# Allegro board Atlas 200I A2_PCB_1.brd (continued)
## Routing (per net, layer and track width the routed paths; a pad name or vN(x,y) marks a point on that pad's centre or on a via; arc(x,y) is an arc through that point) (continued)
PHY0_MDI2_P: length 29.3
  TOP w0.508: T19.20 v1(10,29.37)
  ART04 w0.356: v1(10,29.37) 9.88,29.24 9.88,28.59 10.78,27.68 10.78,27.01 11.14,26.65 11.52,26.65 11.88,26.3 11.88,25.59 11.52,25.23 11.14,25.23 10.78,24.88 10.78,21.94 11.14,21.58 11.58,21.58 11.93,21.23 11.93,20.51 11.58,20.16 11.14,20.16 9.61,18.63 9.61,16.84 11,15.45 11.49,15.45 11.85,15.81 11.85,15.86 12.21,16.22 12.92,16.22 13.27,15.86 13.27,15.81 13.63,15.45 16.92,15.45 18.69,13.69 J17.4
PHY0_MDI3_N: length 40.1
  TOP w0.508: T19.22 v1(12,29.37)
  ART03 w0.356: J17.8 23.77,14.03 22.36,15.43 10.55,15.43 9.56,16.42 9.56,18.76 10.83,20.04 10.83,24.93 12.17,26.26 13.94,26.26 15.7,28.02 15.7,30.31 14.9,31.11 13.06,31.11 12.15,30.2 12.15,29.51 v1(12,29.37)
PHY0_MDI3_P: length 40.1
  TOP w0.508: T19.23 v1(13,29.37)
  ART03 w0.356: v1(13,29.37) 12.91,29.46 12.91,29.88 13.38,30.35 14.58,30.35 14.94,29.99 14.94,28.34 13.62,27.03 11.85,27.03 10.07,25.24 10.07,20.35 8.79,19.07 8.79,16.11 10.23,14.67 11.11,14.67 11.37,14.4 12.64,14.4 12.91,14.67 22.05,14.67 22.5,14.22 J17.7
PHY1_MDI0_N: length 41.9
  TOP w0.508: T20.13 v1(18.93,29.37)
  ART03 w0.356: v1(18.93,29.37) 18.93,29.82 20.54,31.44 31.25,31.44 32.31,30.37 32.72,29.42 32.72,26.06 28.79,22.13 28.53,21.51 28.53,20.77 29.89,19.41 29.89,16.29 28.74,15.13 25.9,15.13 23.59,17.44 23.02,17.44 J17.10
PHY1_MDI0_P: length 41.8
  TOP w0.508: T20.14 v1(19.93,29.37)
  ART03 w0.356: v1(19.93,29.37) 19.93,29.74 20.86,30.67 30.93,30.67 31.67,29.94 31.96,29.27 31.96,28.91 31.6,28.55 31.54,28.55 31.18,28.19 31.18,27.48 31.54,27.13 31.6,27.13 31.96,26.77 31.96,26.38 30.46,24.88 29.96,24.88 29.41,25.44 28.9,25.44 28.4,24.93 28.4,24.43 28.95,23.88 28.96,23.37 28.15,22.56 27.77,21.66 27.77,20.46 29.13,19.1 29.13,16.6 28.42,15.9 26.21,15.9 25.58,16.52 25.58,17.03 25.82,17.27 25.82,17.77 25.32,18.27 24.82,18.27 24.58,18.03 24.07,18.03 23.77,18.34 J17.9
PHY1_MDI1_N: length 15.4
  TOP w0.508: T20.16 v1(21.93,29.37)
  ART04 w0.356: v1(21.93,29.37) 22.03,29.26 22.03,27.64 19.58,25.19 17.42,19.96 J17.14
PHY1_MDI1_P: length 15.4
  TOP w0.508: T20.17 v1(22.93,29.37)
  ART04 w0.356: v1(22.93,29.37) 22.8,29.23 22.8,27.32 22.36,26.89 22.36,26.39 22.76,25.99 22.76,25.49 22.26,24.98 21.76,24.98 21.36,25.38 20.85,25.38 20.23,24.76 19.2,22.29 19.2,21.6 19.61,20.63 20.78,19.46 J17.11
PHY1_MDI2_N: length 29.7
  TOP w0.508: T20.19 v1(24.93,29.37)
  ART04 w0.356: J17.13 19.17,19.46 21.21,17.42 21.21,16.04 21.86,15.38 28.24,15.38 29.26,16.4 29.26,19.04 27.81,20.49 27.81,25.52 25.04,28.29 25.04,29.26 v1(24.93,29.37)
PHY1_MDI2_P: length 29.8
  TOP w0.508: T20.20 v1(25.93,29.37)
  ART04 w0.356: J17.12 20.45,16.43 20.45,15.72 21.55,14.62 28.56,14.62 30.02,16.08 30.02,19.36 28.57,20.81 28.57,23.15 28.93,23.5 29.21,23.5 29.57,23.86 29.57,24.57 29.21,24.93 28.93,24.93 28.57,25.28 28.57,25.84 25.8,28.61 25.8,29.24 v1(25.93,29.37)
PHY1_MDI3_N: length 23.8
  TOP w0.508: T20.22 v1(27.93,29.37)
  ART03 w0.356: v1(27.93,29.37) 27.93,28.45 26.95,27.47 22.29,27.47 16.89,22.07 15.29,22.07 13.9,20.68 13.9,18.91 14.88,17.93 J17.16
PHY1_MDI3_P: length 23.8
  TOP w0.508: T20.23 v1(28.93,29.37)
  ART03 w0.356: J17.15 16.15,19.41 15.55,18.82 15.07,18.82 14.66,19.23 14.66,20.36 15.61,21.31 17.2,21.31 18.58,22.69 18.66,22.69 19.16,22.69 19.88,23.4 19.88,23.48 19.88,23.98 20.59,24.7 20.67,24.7 21.17,24.7 21.89,25.41 21.89,25.49 21.89,26 22.6,26.71 27.27,26.71 28.93,28.37 v1(28.93,29.37)
POWER_EN: length 17.6
  TOP w0.203: v1(103.58,53.19) 103,53.76 J16.301 ; R480.1 104.19,43.76 103.81,43.39 103.34,43.39 103.29,43.43 U16.1
  TOP w0.254: v1(103.48,43.89) 103.48,43.97 103.89,44.37 R480.1
  ART04 w0.203: v1(103.58,53.19) 102.54,52.15 102.54,49.28 104.1,47.71 104.1,44.52 v1(103.48,43.89)
PWM1: length 29.9
  TOP w0.203: J16.286 106.25,50.54 105.97,50.81 105.97,52.54 v1(107.64,54.2) ; R676.1 v1(120.11,68.23)
  ART03 w0.203: v1(107.64,54.2) 108.42,54.2 108.55,54.08 111.34,54.08 113.72,56.46 113.72,60.92 118.92,66.12 118.92,67.88 118.77,68.03 118.77,68.43 119.05,68.72 119.63,68.72 v1(120.11,68.23)
PWM1_R: length 40.7
  TOP w0.203: R443.1 122.94,101.6 v1(122.87,101.6) ; v1(119.08,78.96) 119.4,78.64 U21.12
  ART03 w0.203: v1(122.87,101.6) 122.87,101.23 121.34,99.69 121.34,90.9 120.46,90.02 114.86,90.02 111.48,86.63 111.48,79.19 112.21,78.46 118.58,78.46 v1(119.08,78.96)
RGMII0_MDCK: length 45.3
  TOP w0.203: R117.1 R118.2 25.45,69.52 25.93,70 R129.1 26.57,70.48 v1(26.57,70.49) ; v1(55.26,46.99) 55.25,47 J16.170
  ART04 w0.203: v1(26.57,70.49) 27.09,69.96 31.34,69.96 40.81,60.5 40.81,58.12 44.32,54.61 46.7,54.61 49.79,51.52 50.37,51.52 51.97,49.91 52.34,49.91 v1(55.26,46.99)
RGMII0_MDIO: length 47
  TOP w0.203: J16.172 54.75,47.51 v1(54.22,46.98) ; R128.1 R119.2 17.39,46.93 17.14,47.17 17.14,48.39 v1(17.02,48.51)
  ART04 w0.203: v1(17.02,48.51) 17.75,49.25 25.61,49.25 27.8,48.34 38.14,48.34 39.73,49.93 39.73,50.23 42.29,52.78 46.92,52.78 50.68,49.02 52.18,49.02 v1(54.22,46.98)
RGMII0_RST: length 38.8
  TOP w0.203: J16.174 54.25,50.49 54.08,50.66 54.08,52.58 v1(54.69,53.19) ; v1(72.06,71.01) R173.2 R568.2 R623.1
  ART03 w0.203: v1(72.06,71.01) 72.06,71.01 71.59,70.53 69.3,70.53 68.56,71.27 66.49,71.27 61.56,66.35 61.56,55.67 59.08,53.19 v1(54.69,53.19)
RGMII0_RST_R: length 86.1
  TOP w0.203: v1(24.43,72.77) R127.1 C264.1 R126.2 ; R615.2 v1(73.88,77.33) ; U1.13 15.28,51.39 v1(16.72,50.43)
  ART03 w0.203: v1(16.72,50.43) 16.72,50.76 16.38,51.1 16.38,56.21 16.48,56.31 16.48,56.72 16.38,56.82 16.38,59.82 16.72,60.15 16.72,60.18 17.3,60.76 17.3,64.49 23.83,71.02 24.71,71.02 25.07,71.38 25.07,72.14 v1(24.43,72.77)
  BOTTOM w0.203: v1(73.88,77.33) 71.85,79.36 53.9,79.36 50.52,75.97 28.22,75.97 25.02,72.77 v1(24.43,72.77)
RGMII0_RXCK: length 5.8
  TOP w0.203: J16.202 47.25,47.17 46.94,46.86 45.15,46.86 44.05,45.75 R111.2
RGMII0_RXD0: length 5
  TOP w0.203: R107.2 45.76,45.61 46.3,46.14 47.23,46.14 48.25,47.16 J16.198
RGMII0_RXD1: length 4.5
  TOP w0.203: J16.196 48.75,47.16 47.38,45.79 46.93,45.79 46.62,45.47 R108.2
RGMII0_RXD2: length 4.1
  TOP w0.203: R109.2 47.47,45.38 49.25,47.16 J16.194
RGMII0_RXD3: length 4
  TOP w0.203: J16.192 49.75,47.03 48.33,45.61 R110.2
RGMII0_RXDV: length 5.3
  TOP w0.203: J16.200 47.75,47.16 47.09,46.5 45.84,46.5 44.91,45.57 R112.2
RGMII0_TXCK: length 51.7
  TOP w0.203: C121.1 v1(49.43,45.97) 50.29,46.84 50.29,46.85 50.75,47.3 J16.188 ; U1.21 16.85,54.59 v1(19,56.74)
  ART03 w0.203: v1(49.43,45.97) 49.43,52.68 47.05,55.06 38.26,55.06 35.9,54.08 33.44,54.08 30.73,52.95 28.33,52.95 27.61,53.67 24.29,53.67 24.11,53.49 24.11,53.21 23.93,53.04 23.68,53.04 23.5,53.21 23.5,53.49 23.33,53.67 23.07,53.67 22.89,53.49 22.89,53.21 22.72,53.04 22.46,53.04 22.28,53.21 22.28,53.49 22.11,53.67 21.67,53.67 19,56.34 v1(19,56.74)
RGMII0_TXD0: length 52.2
  TOP w0.203: U1.19 17.78,53.79 v1(20.73,56.74) ; C128.1 v1(51.16,45.97) 51.75,46.57 J16.184
  ART03 w0.203: v1(51.16,45.97) 51.16,49.18 51.34,49.36 51.34,50.59 50.93,51 50.93,52.96 49.48,54.41 49.48,54.91 49.2,55.19 48.7,55.19 47.62,56.27 38.02,56.27 35.88,55.39 35.87,55.38 35.66,55.3 31.48,55.3 30.25,55.8 26.31,55.8 25.4,54.89 22.17,54.89 20.73,56.33 v1(20.73,56.74)
RGMII0_TXD1: length 53
  TOP w0.203: v1(21.59,56.74) 18.24,53.39 U1.18 ; C135.1 v1(52.02,45.97) 52.25,46.2 J16.182
  ART03 w0.203: v1(21.59,56.74) 21.59,56.34 22.43,55.5 25.15,55.5 26.06,56.41 30.37,56.41 31.6,55.91 35.53,55.91 37.89,56.88 47.87,56.88 48.95,55.8 49.45,55.8 50.09,55.16 50.09,54.83 51.54,53.39 51.54,51.59 52.02,51.11 v1(52.02,45.97)
RGMII0_TXD2: length 53.7
  TOP w0.203: v1(22.45,56.74) 18.7,52.99 U1.17 ; C150.1 v1(52.88,45.97) 52.75,46.11 J16.180
  ART03 w0.203: v1(22.45,56.74) 23.09,56.11 24.89,56.11 25.81,57.02 30.62,57.02 31.85,56.52 35.41,56.52 37.77,57.49 48.12,57.49 49.2,56.41 49.71,56.41 50.7,55.42 50.7,55.09 52.15,53.64 52.15,51.87 52.63,51.38 52.63,46.59 v1(52.88,45.97)
RGMII0_TXD3: length 55
  TOP w0.203: U1.16 19.17,52.59 23.32,56.74 v1(23.32,56.74) ; C151.1 v1(53.75,45.97) 53.25,46.47 J16.178
  ART03 w0.203: v1(53.75,45.97) 53.24,47.2 53.24,52 52.86,52.38 52.86,54.54 50.27,57.12 49.53,57.12 48.55,58.1 37.65,58.1 35.29,57.12 31.97,57.12 30.75,57.63 25.56,57.63 24.67,56.74 v1(23.32,56.74)
RGMII0_TXEN: length 51.4
  TOP w0.203: J16.186 51.25,46.77 50.45,45.97 v1(50.29,45.97) C122.1 ; v1(19.86,56.74) 17.31,54.19 U1.20
  ART03 w0.203: v1(50.29,45.97) 50.29,49.17 50.73,49.62 50.73,50.33 50.29,50.77 50.29,52.74 47.36,55.67 38.14,55.67 36,54.78 35.78,54.69 31.36,54.69 30.13,55.19 26.59,55.19 25.68,54.28 21.92,54.28 19.86,56.34 v1(19.86,56.74)
RGMII1_MDCK: length 22.5
  TOP w0.203: v1(66.5,35.89) 67.02,35.89 R176.1 67.25,35.66 R175.2 ; J16.134 64.25,49.74 64.45,49.95 64.74,49.95 65.02,49.66 v1(65.02,48.77)
  TOP w0.254: v1(66.5,35.89) R183.1
  BOTTOM w0.203: v1(65.02,48.77) 65.23,48.97 66.37,48.97 67.27,48.07 67.27,45.17 69.06,43.38 69.06,37.99 66.96,35.89 v1(66.5,35.89)
RGMII1_MDIO: length 19.2
  TOP w0.203: v1(65.02,47.88) 65.02,47.5 64.82,47.3 63.95,47.3 63.75,47.5 J16.136 ; v1(66.5,36.74) 66.56,36.68 R174.2
  TOP w0.254: v1(66.5,36.74) R182.1
  BOTTOM w0.203: v1(65.02,47.88) 65.51,48.36 66.11,48.36 66.66,47.82 66.66,44.92 68.05,43.53 68.05,37.83 66.96,36.74 v1(66.5,36.74)
RGMII1_RST: length 54.5
  TOP w0.203: R564.2 R622.1 R200.2 69.5,77.28 v1(69.49,77.29) ; v1(64.87,52.74) 64.87,52.28 63.25,50.66 J16.138
  ART03 w0.203: v1(53.31,68.11) v1(53.31,77)
  ART04 w0.203: v1(53.31,68.11) 54.75,68.11 64.54,58.32 64.54,56.91 64.87,56.58 v1(64.87,52.74)
  BOTTOM w0.203: v1(69.49,77.29) 68.03,78.75 55.07,78.75 v1(53.31,77)
RGMII1_RST_R: length 90
  TOP w0.203: v1(68.12,34.37) 67.94,34.19 66.93,34.19 66.65,33.91 66.65,32.84 66.45,32.64 65.05,32.64 ; 65.05,32.64 R195.1 C265.1 ; 65.05,32.64 R194.2 64.5,31.44 61.88,31.44 61.35,31.96 U2.13 ; R614.2 v1(73.88,78.44)
  ART03 w0.203: v1(51.18,78.61) 50.86,78.29 50.86,69.29 v1(52.04,68.11)
  ART04 w0.203: v1(68.12,34.37) 68.12,41.39 66.44,43.07 65.54,45.25 65.54,46.01 64.76,46.79 61.77,46.79 51.59,56.97 51.59,67.65 v1(52.04,68.11)
  BOTTOM w0.203: v1(51.18,78.61) 52.3,78.61 54.63,80.94 71.37,80.94 v1(73.88,78.44)
RGMII1_RXCK: length 12.8
  TOP w0.203: J16.166 56.25,47 v1(56.26,46.99)
  TOP w0.254: v1(61.89,42.58) R159.2
  BOTTOM w0.203: v1(56.26,46.99) 56.26,43.92 57.4,42.77 59.23,42.77 59.43,42.57 59.43,42.14 59.64,41.94 60.04,41.94 60.25,42.14 60.25,42.57 60.45,42.77 61.69,42.77 v1(61.89,42.58)
RGMII1_RXD0: length 13.4
  TOP w0.203: v1(57.28,45.97) 57.28,46.1 57.25,46.13 J16.162
  TOP w0.254: v1(64.97,43.21) R163.2
  BOTTOM w0.203: v1(57.28,45.97) 59.06,44.19 61.26,44.19 62.23,43.21 62.74,43.21 62.94,43.01 62.94,42.55 63.14,42.34 63.55,42.34 63.75,42.55 63.75,43.01 63.96,43.21 v1(64.97,43.21)
RGMII1_RXD1: length 9.9
  TOP w0.203: v1(57.78,46.99) 57.75,47.02 J16.160
  TOP w0.254: v1(64.97,45.75) R162.2
  BOTTOM w0.203: v1(57.78,46.99) 58.27,46.51 63.15,46.51 64.96,45.76 v1(64.97,45.75)
RGMII1_RXD2: length 12.5
  TOP w0.203: J16.158 58.25,47.41 58.29,47.36 v1(58.29,45.97)
  TOP w0.254: v1(65.61,42.58) R161.2
  BOTTOM w0.203: v1(65.61,42.58) 65.61,43.26 65.01,43.86 64.08,43.86 62.96,44.98 59.21,44.98 58.29,45.9 v1(58.29,45.97)
RGMII1_RXD3: length 17
  TOP w0.203: J16.156 58.75,47.04 v1(58.8,46.99)
  TOP w0.254: v1(66.5,39.41) R160.2
  BOTTOM w0.203: v1(66.5,39.41) 66.29,39.61 66.29,44.15 65.99,44.45 65.99,45.95 64.62,47.31 59.12,47.31 v1(58.8,46.99)
RGMII1_RXDV: length 15.9
  TOP w0.203: J16.164 56.75,46.75 56.39,46.39 54.69,46.39 54.39,46.09 54.39,45.52 54.59,45.31 54.99,45.31 55.19,45.52 55.19,45.77 55.4,45.98 55.8,45.98 56,45.77 56,45.52 56.21,45.31 58.53,45.31 58.73,45.11 58.73,44.69 58.56,44.51 58.47,44.51 58.29,44.33 58.29,44.08 58.47,43.9 58.56,43.9 58.73,43.73 58.73,43.32 59.29,42.77 59.54,42.77 59.72,42.95 59.72,43.38 59.94,43.6 60.22,43.6 60.4,43.43 60.4,42.89 R158.2
RGMII1_TXCK: length 20.3
  TOP w0.203: J16.152 59.75,46.21 v1(59.33,45.79) ; v1(63.37,35.46) 62.87,35.96 62.3,35.96 61.5,35.16 U2.21
  TOP w0.254: C154.1 59.39,45.21 59.39,45.73 v1(59.33,45.79)
  ART03 w0.203: v1(63.37,35.46) 62.89,34.98 62.05,34.98 60.09,36.94 60.09,39.22 59.81,39.49 59.81,43.91 59.33,44.39 v1(59.33,45.79)
RGMII1_TXD0: length 19.6
  TOP w0.203: v1(61.06,45.79) 60.75,46.09 J16.148 ; v1(63.37,34.37) 62.89,34.85 62.26,34.85 61.77,34.36 U2.19
  TOP w0.254: v1(61.06,45.79) C160.1
  ART03 w0.203: v1(63.37,34.37) 63.96,34.95 63.96,35.77 62.79,36.93 62.79,38.06 62.64,38.2 62.64,38.94 61.41,40.18 61.41,42.78 61.54,42.91 61.54,43.91 61.06,44.39 v1(61.06,45.79)
RGMII1_TXD1: length 20.4
  TOP w0.203: J16.146 61.25,46.46 v1(61.92,45.79) ; v1(62.56,34.37) 62.33,34.37 61.93,33.96 U2.18
  TOP w0.254: v1(61.92,45.79) C166.1
  ART03 w0.203: v1(61.92,45.79) 61.92,44.39 62.15,44.16 62.15,43 63.25,41.9 63.25,38.91 64.57,37.6 64.57,34.7 63.75,33.88 63.04,33.88 v1(62.56,34.37)
RGMII1_TXD2: length 21.4
  TOP w0.203: v1(62.78,45.79) 61.75,46.82 J16.144 ; U2.17 62.09,33.56 62.26,33.73 62.92,33.73 v1(63.37,33.27)
  TOP w0.254: v1(62.78,45.79) C174.1
  ART03 w0.203: v1(63.37,33.27) 64.01,33.27 65.18,34.44 65.18,37.85 63.86,39.16 63.86,43.31 62.78,44.39 v1(62.78,45.79)
RGMII1_TXD3: length 22.4
  TOP w0.203: J16.142 62.25,47.35 63.65,45.95 C178.1 ; U2.16 62.45,33.16 v1(62.56,33.27)
  TOP w0.254: v1(64.28,45.15) C178.1
  ART03 w0.203: v1(62.56,33.27) 63.17,32.66 64.26,32.66 65.79,34.19 65.79,38.1 64.49,39.4 64.49,43.87 64.77,44.14 64.77,44.67 v1(64.28,45.15)
RGMII1_TXEN: length 16.9
  TOP w0.203: v1(62.56,35.46) 62.31,35.46 61.61,34.76 U2.20 ; J16.150 60.25,45.84 v1(60.19,45.79)
  TOP w0.254: v1(60.19,45.79) C159.1
  ART03 w0.203: v1(62.56,35.46) 62.56,35.92 62.18,36.3 62.18,37.81 61.23,38.75 61.23,39.06 60.42,39.87 60.42,44.16 60.19,44.39 v1(60.19,45.79)
RGMII_CLK_PHY0: length 60.4
  TOP w0.203: R96.2 v1(42.88,41.2) R100.1 43.26,41.83 43.51,42.09 43.51,43.48 44.05,44.03 R111.1 ; C109.1 12.19,59.03 12.7,58.52 v1(12.7,58.17) 12.75,58.11 U1.28
  ART03 w0.203: v1(42.88,41.2) 42.65,41.43 41.96,41.43 41.43,40.89 40.92,40.89 40.77,41.05 40.77,41.43 40.56,41.63 39.91,41.63 39.7,41.43 39.7,41.07 39.5,40.87 39.09,40.87 38.89,41.07 38.89,41.43 38.69,41.63 38.28,41.63 38.08,41.43 38.08,41.07 37.87,40.87 37.47,40.87 37.26,41.07 37.26,41.43 37.06,41.63 36.66,41.63 36.45,41.43 36.45,41.07 36.25,40.87 35.84,40.87 35.64,41.07 35.64,41.43 35.44,41.63 35.11,41.63 35.08,41.66 34.9,41.66 34.7,41.86 34.7,42.14 34.16,42.67 31.24,42.67 30.44,43.21 27.9,43.21 27.7,43.41 27.7,43.87 27.5,44.07 27.09,44.07 26.89,43.87 26.89,43.41 26.68,43.21 26.28,43.21 26.07,43.41 26.07,43.87 25.87,44.07 25.46,44.07 25.26,43.87 25.26,43.41 25.06,43.21 24.65,43.21 24.45,43.41 24.45,43.87 24.25,44.07 23.84,44.07 23.64,43.87 23.64,43.41 23.43,43.21 23.03,43.21 22.82,43.41 22.82,43.87 22.62,44.07 22.21,44.07 22.01,43.87 22.01,43.41 21.81,43.21 19.77,43.21 17.2,44.27 16.1,45.36 16.1,46.15 15.13,47.12 14.12,47.12 12.3,48.94 12.3,55.1 12.7,55.5 v1(12.7,58.17)
RGMII_CLK_PHY1: length 9.1
  TOP w0.203: v1(59.12,38.07) 59.12,37.87 58.91,37.67 U2.28 ; v1(62.7,39.81) 63.34,40.45 R177.1 R152.2 R159.1
  TOP w0.254: v1(62.7,39.81) C44.1
  BOTTOM w0.203: v1(62.7,39.81) 62.19,39.81 60.45,38.07 v1(59.12,38.07)
RGMII_DV_PHY0: length 57.3
  TOP w0.203: v1(13.21,58.93) 13.31,58.83 13.31,57.96 13.15,57.81 U1.27 ; R92.2 44.15,41.19 v1(44.14,41.2) 44.15,41.21 R120.1 44.54,41.83 44.78,42.07 44.78,43.69 44.91,43.81 R112.1
  ART03 w0.203: v1(13.21,58.93) 13.03,59.11 11.79,59.11 11.28,58.6 9.83,55.1 9.83,50.54 10.74,48.34 11.3,47.78 11.3,46.6 11.51,46.39 11.51,46.37 12.13,45.75 12.15,45.75 13.36,44.54 20.2,41.71 30.49,41.71 32.2,40.56 32.48,40.56 33.04,40 33.3,39.83 35.63,39.37 40.06,39.37 43.89,40.95 v1(44.14,41.2)
RGMII_DV_PHY1: length 9.4
  TOP w0.203: U2.27 59.31,37.57 59.88,38.14 59.88,38.6 60.2,38.91 60.5,38.91 60.71,38.71 60.71,38.51 60.88,38.33 61.21,38.33 61.54,38.65 61.54,39.1 61.33,39.31 60.67,39.31 60.47,39.51 R181.1 R148.2 60.47,41.86 61.15,42.55 R158.1
RGMII_PHY0_D0: length 55.9
  TOP w0.203: U1.26 13.55,57.37 v1(13.72,57.53) ; R107.1 45.76,43.9 46.05,43.61 46.05,42.16 45.72,41.83 R141.1 45.43,41.81 45.43,41.22 v1(45.45,41.2) 45.43,41.18 45.43,40.58 R90.2
  ART03 w0.203: v1(45.45,41.2) 45.13,41.52 45.11,41.52 44.93,41.71 43.23,41.71 42.9,42.04 41.15,42.04 40.59,42.6 35.1,42.6 34.39,43.31 31.39,43.31 30.63,43.81 28.83,43.81 27.97,44.68 27.15,44.68 26.95,44.88 26.95,45.77 26.75,45.97 26.34,45.97 26.14,45.77 26.14,44.88 25.93,44.68 25.53,44.68 25.32,44.88 25.32,45.77 25.12,45.97 24.71,45.97 24.51,45.77 24.51,44.88 24.31,44.68 23.84,44.68 23.63,44.88 23.63,45.59 23.43,45.8 23.02,45.8 22.82,45.59 22.82,44.88 22.62,44.68 17.93,44.68 16.71,45.9 16.71,46.41 15.4,47.73 14.37,47.73 13.51,48.6 13.51,57.32 v1(13.72,57.53)
RGMII_PHY0_D1: length 63.3
  TOP w0.203: R108.1 46.62,44.06 47.32,43.36 47.32,42.06 47.09,41.83 R123.1 v1(46.69,41.2) R93.2 ; U1.25 13.95,57.01 14.22,57.28 v1(14.22,58.29)
  ART03 w0.203: v1(14.22,58.29) 14.22,58.77 13.28,59.72 11.53,59.72 10.76,58.95 9.22,55.22 9.22,50.29 9.98,48.47 9.98,47.86 10.56,46.46 11.83,45.19 11.85,45.19 13.16,43.88 20.05,41.03 30.41,41.03 32.02,39.95 32.23,39.95 32.51,39.67 32.51,39.62 33.05,39.26 35.57,38.76 40.42,38.76 45.02,40.67 45.69,40.67 46.48,40.99 v1(46.69,41.2)
RGMII_PHY0_D2: length 61.1
  TOP w0.203: R94.2 v1(47.96,41.2) R122.1 48.29,41.83 48.59,42.14 48.59,43.29 48.14,43.74 47.96,43.74 47.47,44.22 R109.1 ; v1(15.21,56.39) 15.08,56.26 15.08,56.01 14.87,55.79 U1.24
  ART03 w0.203: v1(47.96,41.2) 47.4,41.2 46.7,41.9 46.02,41.9 45.75,42.17 45.75,42.44 45.47,42.72 44.64,42.72 44.26,42.35 43.83,42.35 43.45,42.72 41.91,42.72 41.88,42.75 41.78,42.75 41.05,43.48 39.92,43.48 39.64,43.21 39.11,43.21 38.83,43.48 38.3,43.48 38.02,43.21 37.48,43.21 37.21,43.48 36.67,43.48 36.39,43.21 35.86,43.21 35.58,43.48 35.07,43.48 34.64,43.92 31.58,43.92 30.76,44.46 30.37,44.46 29.68,45.15 29.68,45.44 30.1,45.86 30.1,46.66 30.05,46.71 30.05,46.74 29.18,47.6 24.26,47.6 22.76,49.1 22.05,49.1 21.79,48.84 21.77,48.84 21.49,48.56 21.49,48.16 21.84,47.81 21.84,45.49 21.64,45.29 18.19,45.29 17.32,46.15 17.32,46.66 15.65,48.34 14.63,48.34 14.13,48.83 14.13,50.59 14.61,51.07 14.61,51.32 14.25,51.67 14.25,52.08 14.45,52.28 14.66,52.28 14.86,52.48 14.86,52.89 14.66,53.09 14.45,53.09 14.25,53.3 14.25,53.7 14.45,53.91 14.66,53.91 14.86,54.11 14.86,54.52 14.66,54.72 14.45,54.72 14.25,54.92 14.25,55.33 14.45,55.53 14.66,55.53 14.86,55.74 14.86,56.04 v1(15.21,56.39)
RGMII_PHY0_D3: length 65.1
  TOP w0.203: U1.23 15.48,55.39 v1(15.65,55.56) ; R95.2 49.38,40.72 v1(49.38,41.2) 49.83,41.66 R121.1 49.4,41.83 49.2,42.04 49.2,43.19 48.33,44.06 R110.1
  ART03 w0.203: v1(15.65,55.56) 15.65,49.22 15.71,49.17 15.71,49.14 18.12,46.73 18.19,46.73 18.47,46.44 18.47,46.38 18.95,45.9 20.6,45.9 21.01,46.3 21.01,47.78 20.88,47.91 20.88,48.81 21.52,49.45 21.54,49.45 21.79,49.71 24.26,49.71 24.57,49.39 24.57,49.11 24.36,48.9 24.36,48.61 24.74,48.23 25.18,48.23 25.39,48.44 25.39,48.74 25.59,48.95 26,48.95 26.2,48.74 26.2,48.44 26.4,48.23 26.81,48.23 27.01,48.44 27.01,48.74 27.22,48.95 27.62,48.95 27.83,48.74 27.83,48.44 28.03,48.23 29.44,48.23 30.9,46.77 30.9,45.3 31.11,45.09 31.78,45.09 32.13,44.73 33.16,44.73 33.36,44.93 33.36,45.64 33.57,45.85 33.97,45.85 34.18,45.64 34.18,44.93 34.38,44.73 34.69,44.73 35.33,44.09 35.74,44.09 35.95,44.3 35.95,44.81 36.15,45.01 36.56,45.01 36.76,44.81 36.76,44.3 36.96,44.09 37.37,44.09 37.57,44.3 37.57,44.81 37.78,45.01 38.18,45.01 38.39,44.81 38.39,44.3 38.59,44.09 39,44.09 39.2,44.3 39.2,44.81 39.4,45.01 39.81,45.01 40.01,44.81 40.01,44.3 40.21,44.09 41.33,44.09 41.71,44.48 42.14,44.48 42.52,44.09 42.95,44.09 43.33,44.48 43.76,44.48 44.14,44.09 44.58,44.09 44.96,44.48 45.39,44.48 45.77,44.09 46,44.09 46.2,43.89 46.2,43.08 46.77,42.51 46.95,42.51 47.52,41.94 48.64,41.94 v1(49.38,41.2)
RGMII_PHY1_D0: length 8.3
  TOP w0.203: R163.1 R147.2 R143.1 64.16,40.41 62.49,38.74 v1(62.16,38.74) 61.39,37.97 60.22,37.97 59.71,37.46 U2.26
RGMII_PHY1_D1: length 15.1
  TOP w0.203: R162.1 R180.1 66.53,44.3 R149.2 ; v1(60.73,37.44) 60.32,37.44 60.11,37.24 U2.25
  TOP w0.254: R149.2 v1(66.95,43.24)
  BOTTOM w0.203: v1(66.95,43.24) 66.98,43.21 66.98,38.3 66.7,38.02 62.13,38.02 v1(60.73,37.44)
RGMII_PHY1_D2: length 10.3
  TOP w0.203: R161.1 R150.2 R179.1 67.06,40.39 66.75,40.08 64.47,40.08 v1(61.41,37.03) 61.41,36.72 61.05,36.36 U2.24
RGMII_PHY1_D3: length 6.9
  TOP w0.203: R160.1 R178.1 R151.2 64.69,37.6 64.39,37.9 63.8,37.9 62.82,37.49 61.29,35.96 U2.23
SD_CLK: length 5.9
  TOP w0.381: J3.5 17.57,97.51 v1(17.88,97.82) 17.88,98.53 18.6,99.25 U3.4 19.73,100.11 19.91,100.29 R171.2
SD_CMD: length 11.2
  TOP w0.203: R226.2 v1(21.82,101.6)
  TOP w0.381: U3.6 19.73,97.11 v1(19.1,96.48) 17.93,95.31 J3.3
  ART03 w0.203: v1(19.1,96.48) 20.07,97.44 20.07,100.46 20.65,101.04 21.26,101.04 v1(21.82,101.6)
SD_DATA0: length 10.2
  TOP w0.203: U4.1 19.5,104.84 19.15,105.18 R227.2
  TOP w0.381: J3.7 17.64,99.71 v1(18,100.07) 19.91,101.98 20.19,101.98 20.95,102.74 20.95,104.45 20.57,104.84 U4.1
SD_DATA1: length 6.7
  TOP w0.381: R228.2 17.68,103.45 18.2,102.94 U4.3 v1(17.96,101.16) 17.6,100.81 J3.8
SD_DATA2: length 9.6
  TOP w0.381: R224.2 24.09,97.35 U3.1 21.87,97.35 21.49,96.97 21.49,96.16 v1(18.78,93.46) 18.43,93.11 J3.1
SD_DATA3: length 10.5
  TOP w0.381: R225.2 24.09,99.25 U3.3 21.59,99.25 20.7,98.36 20.7,96.49 v1(19.9,95.7) 18.42,94.21 J3.2
SDIO_CLK: length 81.8
  TOP w0.203: R309.1 R308.2 23.44,102.08 21.28,102.08 20.73,101.53 R171.1 ; J16.169 v1(55.5,58.83)
  TOP w0.381: R171.1 20.73,100.56 v1(20.95,100.33)
  ART03 w0.203: v1(55.5,58.83) 55.5,58.86 54.88,59.49 54.85,59.49 53.98,60.36 53.98,80.02 48.3,85.7 47.13,85.7 v1(45.42,87.41)
  ART04 w0.203: v1(45.42,87.41) 44.71,88.11 43.89,88.11 41.71,90.3 41.71,91.34 41.22,91.83 41.22,92.12 41.5,92.4 41.5,92.69 41.22,92.97 40.93,92.97 40.65,92.69 40.36,92.69 40.07,92.98 40.07,93.27 40.35,93.55 40.35,93.84 40.07,94.12 39.78,94.12 39.5,93.84 39.21,93.84 38.92,94.13 38.92,94.42 39.2,94.7 39.2,94.98 38.92,95.27 38.63,95.27 38.35,94.99 38.06,94.99 37.77,95.28 37.77,95.57 38.05,95.85 38.05,96.13 37.77,96.42 37.48,96.42 37.2,96.14 36.91,96.14 36.62,96.43 36.62,96.72 36.9,97 36.9,97.28 36.7,97.49 36.41,97.49 35.79,96.86 35.14,96.86 34.94,97.07 34.94,97.56 34.73,97.76 34.33,97.76 34.12,97.56 34.12,97.07 33.92,96.86 33.52,96.86 33.31,97.07 33.31,97.56 33.11,97.76 32.7,97.76 32.5,97.56 32.5,97.07 32.3,96.86 31.89,96.86 31.69,97.07 31.69,97.56 31.48,97.76 31.08,97.76 30.87,97.56 30.87,97.07 30.67,96.86 29.81,96.86 28.06,98.62 24.5,98.62 22.79,100.33 v1(20.95,100.33)
SDIO_CLK_R: length 13.7
  TOP w0.203: R86.2 v1(26.04,86.36) ; J2.9 20.17,79.64 v1(20.4,79.86)
  ART03 w0.203: v1(26.04,86.36) 26.77,85.62 26.77,83.26 23.55,80.04 20.57,80.04 v1(20.4,79.86)
SDIO_CMD: length 68
  TOP w0.203: v1(23.5,100.33) 23.5,100.71 R233.2 R226.1 ; v1(56,59.71) J16.167
  ART03 w0.203: v1(56,59.71) 55.12,60.59 55.12,79.74 48.55,86.31 47.42,86.31 46.81,86.92 v1(46.81,87.41)
  ART04 w0.203: v1(46.81,87.41) 46.81,88.27 45.12,89.97 43.97,89.97 43.15,90.78 43.15,92.86 35.97,100.05 26.59,100.05 26.24,99.69 24.79,99.69 24.16,100.33 v1(23.5,100.33)
SDIO_CMD_R: length 19.6
  TOP w0.203: J2.11 19.68,79.95 19.76,80.04 v1(19.76,81.13) ; R85.2 v1(25.97,92.08)
  ART03 w0.203: v1(25.97,92.08) 25.37,91.48 25.37,83.72 23.65,81.99 23.65,81.56 22.73,80.64 20.24,80.64 v1(19.76,81.13)
SDIO_DATA0: length 74.9
  TOP w0.203: J16.165 v1(56.5,58.83) ; v1(20.95,106.43) 20.95,106.38 20.75,106.17 R227.1 R232.2
  ART03 w0.203: v1(45.54,91.73) 45.42,91.73 44.75,91.07 44.75,88.78 45.52,88.02 45.67,88.02 47.06,88.02 47.52,87.56 47.52,87.21 47.81,86.92 48.8,86.92 55.73,79.99 55.73,60.83 56.5,60.06 v1(56.5,58.83)
  ART04 w0.203: v1(20.95,106.43) 30.28,102.57 36.3,102.57 45.54,93.32 v1(45.54,91.73)
SDIO_DATA0_R: length 13.5
  TOP w0.203: J2.13 19.17,80.44 v1(18.49,81.13) ; R84.2 v1(24.77,86.36)
  ART03 w0.203: v1(24.77,86.36) 24.77,84.41 24.28,83.92 22.28,83.92 20.09,81.74 19.51,81.74 18.9,81.13 v1(18.49,81.13)
SDIO_DATA1: length 76.7
  TOP w0.203: R228.1 R231.2 16.51,104.9 16.12,104.51 v1(16.12,104.15) ; J16.163 v1(57,59.71)
  ART03 w0.203: v1(46.81,89.19) 47.99,88.01 48.57,88.01 56.34,80.25 56.34,61.47 57,60.81 v1(57,59.71)
  ART04 w0.203: v1(16.12,104.15) 20.87,102.18 21.82,102.18 24.95,100.89 36.07,100.89 43.79,93.17 43.79,91.52 44.67,90.64 45.36,90.64 v1(46.81,89.19)
SDIO_DATA1_R: length 18.9
  TOP w0.203: v1(18.49,79.86) 18.68,79.67 J2.15 ; R83.2 v1(24.7,92.08)
  ART03 w0.203: v1(24.7,92.08) 24.16,91.53 24.16,85.7 22.98,84.53 22.02,84.53 19.84,82.35 19.26,82.35 18.65,81.74 18.24,81.74 17.88,81.38 17.88,80.47 v1(18.49,79.86)
SDIO_DATA2: length 71.3
  TOP w0.203: J16.161 v1(57.5,58.84) ; v1(26.87,99.39) 25.68,98.2 R230.2 R224.1
  ART03 w0.203: v1(57.5,58.84) 57.5,62.27 56.95,62.82 56.95,80.5 48.82,88.62 48.24,88.62 47.06,89.8 46.41,89.8 v1(45.42,88.81)
  ART04 w0.203: v1(45.42,88.81) 44.93,89.29 43.78,89.29 42.39,90.68 42.39,92.66 35.66,99.39 34.33,99.39 34.13,99.19 34.13,98.73 33.93,98.53 33.52,98.53 33.32,98.73 33.32,99.19 33.11,99.39 32.71,99.39 32.5,99.19 32.5,98.73 32.3,98.53 31.89,98.53 31.69,98.73 31.69,99.19 31.49,99.39 31.08,99.39 30.88,99.19 30.88,98.73 30.67,98.53 30.27,98.53 30.06,98.73 30.06,99.19 29.86,99.39 v1(26.87,99.39)
SDIO_DATA2_R: length 13
  TOP w0.203: R82.2 v1(23.5,86.36) ; v1(17.22,81.13) 17.88,80.47 17.88,79.82 18.17,79.53 J2.17
  ART03 w0.203: v1(23.5,86.36) 23.5,85.91 22.73,85.14 21.77,85.14 19.59,82.96 19,82.96 18.39,82.35 17.99,82.35 17.27,81.63 17.27,81.18 v1(17.22,81.13)
SDIO_DATA3: length 71
  TOP w0.203: R225.1 R229.2 25.2,100.1 25.4,100.3 25.4,100.97 v1(26.04,101.6) ; J16.159 v1(58,59.7)
  ART03 w0.203: v1(58,59.7) 58,62.73 57.56,63.17 57.56,80.75 49.08,89.23 48.49,89.23 47.32,90.41 46.86,90.41 v1(46.81,90.46)
  ART04 w0.203: v1(46.81,90.46) 46.02,91.25 45.15,91.25 44.86,91.54 44.86,93.07 36.32,101.6 29.34,101.6 29.14,101.8 29.14,102.23 28.94,102.44 28.53,102.44 28.33,102.23 28.33,101.8 28.12,101.6 27.72,101.6 27.51,101.8 27.51,102.23 27.31,102.44 26.9,102.44 26.7,102.23 26.7,101.8 26.5,101.6 v1(26.04,101.6)
SDIO_DATA3_R: length 19.3
  TOP w0.203: J2.19 17.68,79.4 v1(17.22,79.86) ; R81.2 v1(23.43,92.08)
  ART03 w0.203: v1(17.22,79.86) 16.66,80.42 16.66,81.89 17.77,83 17.77,83.58 18.06,83.86 19.63,83.86 21.52,85.75 22.48,85.75 22.86,86.13 22.86,91.5 v1(23.43,92.08)
SDIO_DETECT: length 77
  TOP w0.203: R234.1 R240.2 21.69,107.82 C104.1 R223.1 20.47,107.67 v1(20.95,107.19) ; J16.155 v1(59,58.85)
  ART03 w0.203: v1(46.81,91.73) 47.53,91.01 48.16,91.01 58.17,81 58.17,63.47 59,62.64 v1(59,58.85)
  ART04 w0.203: v1(20.95,107.19) 30.28,103.33 36.65,103.33 46.18,93.8 46.18,92.36 v1(46.81,91.73)
SDIO_POWER_EN: length 85.6
  TOP w0.203: R1.1 v1(42.62,117.53) ; v1(49.71,82.93) 49.25,82.47 49.25,77.75 42.6,71.09 v1(42.6,69.32) ; J16.157 58.5,54.46 v1(58.5,54.46)
  ART04 w0.203: v1(42.6,69.32) 51.52,69.32 52.68,68.15 52.68,67.18 60.49,59.37 60.49,58.85 59.74,58.11 59.74,55.7 v1(58.5,54.46) ; v1(49.71,82.93) 50.42,83.64 50.42,105.51 42.62,113.3 v1(42.62,117.53)
SDIO_VOUT: length 90.8
  TOP w0.254: R231.1 18.16,104.9 18.41,105.16 v1(18.41,105.28) 18.41,106.55 18.92,107.06 R232.1 ; v1(26.11,100.25) 26.11,99.88 25.52,99.29 R229.1 ; R233.1 24.54,101.37 v1(24.77,101.6) 24.54,101.83 R308.1 ; v1(23.11,106.93) 22.99,107.06 R240.1 ; v1(59.5,59.68) J16.153
  TOP w0.381: v1(26.67,97.92) 26.14,97.38 R230.1
  ART03 w0.254: v1(18.41,105.28) 18.41,105.77 20.35,107.7 22.35,107.7 v1(23.11,106.93)
  ART03 w0.381: v1(24.77,101.6) v1(26.11,100.25) 26.11,98.48 v1(26.67,97.92) ; v1(38.56,93.51) 39.63,92.43 49.25,92.43 59.5,82.18 v1(59.5,59.68)
  ART04 w0.381: v1(38.56,93.51) 35.9,96.16 29.52,96.16 27.77,97.92 v1(26.67,97.92)
  BOTTOM w0.254: v1(24.77,101.6) 24.77,103.68 23.11,105.33 v1(23.11,106.93)
SERDES0_RX_N: length 56.1
  TOP w0.188: v1(88.46,45.12) 88.19,45.4 88.19,47.63 88.25,47.7 J16.38 ; R30.1 v1(110.52,35.15)
  ART04 w0.173: v1(110.52,35.15) 110.2,35.47 109.48,35.47 108.23,36.72 108.23,41.97 108.97,42.7 108.97,45.24 109.73,46 109.73,52.5 109.01,53.21 106.35,53.21 105.54,54.03 105.54,54.61 104.78,55.37 89.95,55.37 89.38,54.8 89.38,54.05 88.19,52.85 88.19,45.39 v1(88.46,45.12)
SERDES0_RX_P: length 57.4
  TOP w0.188: v1(87.54,45.12) 87.81,45.39 87.81,47.67 87.75,47.72 J16.40 ; R31.1 v1(110.52,36.17)
  ART04 w0.173: v1(87.54,45.12) 87.81,45.39 87.81,53.01 89,54.2 89,54.96 89.8,55.75 104.93,55.75 105.92,54.77 105.92,54.18 106.51,53.59 109.17,53.59 110.11,52.66 110.11,45.85 109.35,45.09 109.35,42.55 108.61,41.81 108.61,39.81 108.78,39.64 108.82,39.64 108.99,39.47 108.99,39.12 108.82,38.95 108.78,38.95 108.61,38.77 108.61,38.43 108.78,38.26 108.82,38.26 108.99,38.08 108.99,37.74 108.82,37.57 108.78,37.57 108.61,37.39 108.61,36.88 109.64,35.85 110.2,35.85 v1(110.52,36.17)
SERDES0_TX_N: length 9
  TOP w0.188: C6.1 92.72,62.55 92.72,61.71 90.39,59.39 88.81,58.74 87.94,57.87 87.94,57.39 88,57.33 J16.39
SERDES0_TX_P: length 9
  TOP w0.188: C1.1 92.33,62.58 92.33,61.87 90.18,59.72 88.6,59.06 87.56,58.02 87.56,57.39 87.5,57.33 J16.41
SERDES1_RX_N: length 70.7
  TOP w0.188: v1(86.96,46.57) 86.69,46.84 86.69,47.28 86.75,47.34 J16.44 ; J1.29 122.45,36.39 122.51,36.34 123.67,36.34 123.67,36.34 124.1,36.34 v1(124.37,36.61)
  ART04 w0.173: v1(124.37,36.61) 124.64,36.34 125.05,36.34 125.45,35.94 125.45,35.15 124.33,34.04 123.22,34.04 121.26,35.99 117.42,35.99 114.22,39.19 114.22,41.33 110.87,44.68 110.87,53.16 108.91,55.12 106.83,55.12 105.53,56.41 89.26,56.41 87.82,54.98 87.82,54.2 86.69,53.06 86.69,46.84 v1(86.96,46.57)
SERDES1_RX_P: length 70.7
  TOP w0.188: v1(124.37,35.68) 124.1,35.96 123.83,35.96 123.83,35.95 122.51,35.95 122.45,35.9 J1.31 ; v1(86.04,46.57) 86.31,46.84 86.31,47.29 86.25,47.34 J16.46
  ART04 w0.173: v1(86.04,46.57) 86.31,46.84 86.31,53.22 87.44,54.35 87.44,55.14 89.1,56.79 105.69,56.79 106.99,55.5 109.07,55.5 111.25,53.32 111.25,44.84 114.6,41.48 114.6,39.34 117.58,36.37 121.42,36.37 122.17,35.62 122.42,35.62 122.55,35.75 122.8,35.75 123.04,35.51 123.04,35.26 122.91,35.13 122.91,34.88 123.37,34.42 124.18,34.42 125.07,35.31 125.07,35.78 124.9,35.96 124.64,35.96 v1(124.37,35.68)
SERDES1_TX_N: length 8.6
  TOP w0.188: C3.1 90.69,62.58 90.69,62 88.76,60.08 88.18,59.84 86.44,58.09 86.44,57.39 86.5,57.33 J16.45
SERDES1_TX_P: length 8.6
  TOP w0.188: C2.1 90.3,62.58 90.3,62.16 88.54,60.4 87.97,60.16 86.06,58.25 86.06,57.39 86,57.33 J16.47
SERDES2_RX_N: length 76.1
  TOP w0.188: v1(85.46,45.12) 85.17,45.42 85.17,47.55 85.25,47.63 J16.50 ; J1.17 122.45,39.39 122.51,39.34 123.67,39.34 123.67,39.34 124.1,39.34 v1(124.37,39.61)
  ART04 w0.173: v1(85.46,45.12) 85.14,45.44 85.14,54.27 84.91,54.5 84.91,57.84 85.81,58.73 99.24,58.73 99.64,58.33 104.84,58.33 106.14,57.79 107.67,56.26 109.92,56.26 112.01,54.17 112.01,45.21 115.37,41.86 119.2,41.86 119.37,41.69 119.37,41.55 119.54,41.38 119.89,41.38 120.06,41.55 120.06,41.69 120.23,41.86 120.58,41.86 120.75,41.69 120.75,41.5 120.92,41.33 121.27,41.33 121.44,41.5 121.44,41.69 121.61,41.86 121.96,41.86 122.13,41.69 122.13,41.5 122.31,41.33 122.65,41.33 122.82,41.5 122.82,41.69 123,41.86 123.39,41.86 124.82,40.44 124.82,39.56 124.65,39.4 124.54,39.4 124.37,39.57 v1(124.37,39.61)
SERDES2_RX_P: length 76.2
  TOP w0.188: v1(84.54,45.12) 84.79,45.37 84.79,47.47 84.75,47.51 J16.52 ; J1.19 122.45,38.9 122.51,38.95 123.83,38.95 123.83,38.96 124.1,38.96 v1(124.37,38.68)
  ART04 w0.173: v1(84.54,45.12) 84.76,45.34 84.76,54.11 84.53,54.34 84.53,57.99 85.65,59.12 99.4,59.12 99.8,58.71 104.91,58.71 106.36,58.12 107.83,56.64 110.08,56.64 112.39,54.33 112.39,45.37 115.52,42.24 123.55,42.24 125.2,40.59 125.2,39.4 124.81,39.01 124.54,39.01 124.37,38.84 v1(124.37,38.68)
SERDES2_TX_N: length 8.2
  TOP w0.188: C25.1 88.66,62.58 88.66,62.14 84.94,58.42 84.94,57.39 85,57.33 J16.51
SERDES2_TX_P: length 8.2
  TOP w0.188: C26.1 88.28,62.58 88.28,62.3 84.56,58.58 84.56,57.39 84.5,57.33 J16.53
SERDES3_RX_N: length 73.9
  TOP w0.188: v1(83.96,46.57) 83.69,46.84 83.69,47.64 83.75,47.7 J16.56 ; J1.5 122.45,42.39 122.51,42.34 124.02,42.34 124.67,42.98 124.67,43.25 v1(124.39,43.52)
  ART04 w0.173: v1(124.39,43.52) 124.67,43.8 124.67,44.36 123.94,45.09 121.73,45.09 121.56,44.92 121.56,44.65 121.39,44.48 121.04,44.48 120.87,44.65 120.87,44.92 120.7,45.09 120.35,45.09 120.18,44.92 120.18,44.65 120.01,44.48 119.66,44.48 119.49,44.65 119.49,44.92 119.31,45.09 118.97,45.09 118.68,44.81 118.22,44.81 117.93,45.09 115.91,45.09 113.16,47.85 113.16,54.52 109.79,57.89 105.7,59.59 100.98,59.59 100.56,60 98.33,60 97.23,61.11 86.64,61.11 83.39,57.86 83.39,51.31 83.69,51.01 83.69,46.84 v1(83.96,46.57)
SERDES3_RX_P: length 73.9
  TOP w0.188: v1(83.04,46.57) 83.31,46.84 83.31,47.66 83.25,47.72 J16.58 ; v1(125.32,43.52) 125.05,43.25 125.05,42.82 124.18,41.95 122.51,41.95 122.45,41.9 J1.7
  ART04 w0.173: v1(125.32,43.52) 125.05,43.79 125.05,44.52 124.1,45.47 116.07,45.47 113.54,48.01 113.54,54.68 110,58.21 105.77,59.97 101.14,59.97 100.72,60.39 98.49,60.39 97.38,61.49 86.48,61.49 83.01,58.02 83.01,51.16 83.31,50.85 83.31,46.84 v1(83.04,46.57)
SERDES3_TX_N: length 8
  TOP w0.188: J16.57 83.5,57.33 83.44,57.39 83.44,58.88 86.64,62.08 86.64,62.59 C21.1
SERDES3_TX_P: length 8
  TOP w0.188: J16.59 83,57.33 83.06,57.38 83.06,59.04 86.26,62.23 86.26,62.56 C22.1
SERDES4_RX_N: length 104.6
  TOP w0.188: J16.86 76.25,47.36 76.19,47.3 76.19,46.93 76.87,46.25 77.98,46.25 v1(78.25,46.52) ; v1(11.24,74.31) 10.67,74.89 10.67,75.72 11.68,76.74 11.68,77.1 11.68,77.1 J2.43
  ART04 w0.173: v1(11.24,74.31) 11.53,74.6 12.27,74.6 13.64,75.97 15.6,75.97 17.12,77.5 18.03,77.5 18.31,77.22 18.72,77.22 19,77.5 21.1,77.5 21.38,77.22 21.79,77.22 22.07,77.5 22.48,77.5 22.76,77.22 23.17,77.22 23.45,77.5 33.62,77.5 35.28,75.84 57.1,75.84 61.47,71.48 67.84,71.48 68.55,70.76 69.44,70.76 70.15,70.05 76.19,70.05 77.25,69.49 78.59,68.15 78.59,51.03 78.89,50.72 78.89,46.42 78.72,46.25 78.52,46.25 v1(78.25,46.52)
SERDES4_RX_P: length 104.6
  TOP w0.188: v1(78.25,45.6) 77.98,45.87 76.71,45.87 75.81,46.77 75.81,47.3 75.75,47.36 J16.88 ; J2.41 12.17,77.1 12.06,76.99 12.06,76.58 11.21,75.72 11.21,75.28 v1(11.24,75.24)
  ART04 w0.173: v1(11.24,75.24) 11.5,74.98 12.11,74.98 13.48,76.35 15.44,76.35 16.96,77.88 33.78,77.88 35.43,76.23 57.26,76.23 61.63,71.86 68,71.86 68.71,71.15 69.6,71.15 70.31,70.43 76.29,70.43 77.48,69.8 78.97,68.31 78.97,51.19 79.27,50.88 79.27,46.27 78.88,45.87 78.52,45.87 v1(78.25,45.6)
SERDES4_TX_N: length 85.8
  TOP w0.188: J16.87 76,56.98 75.95,57.03 75.95,58.46 76.14,58.65 76.34,58.65 76.5,58.48 v1(76.5,58.4) ; C42.1 13.03,74.85 13.03,73.22 v1(12.8,72.98)
  ART04 w0.173: v1(12.8,72.98) 13.09,73.27 13.09,74.02 13.97,74.9 16.33,74.9 17.95,76.52 31.05,76.52 32.44,75.13 56.16,75.13 61.42,69.88 68.85,69.88 69.42,69.31 69.9,68.98 69.96,68.96 76.61,68.96 77.55,68.02 77.55,59.05 77.22,58.72 77.14,58.69 77.08,58.67 76.77,58.67 v1(76.5,58.4)
SERDES4_TX_P: length 86
  TOP w0.188: C41.1 13.41,75.03 13.41,73.3 v1(13.72,72.98) ; J16.89 75.5,56.95 75.56,57.01 75.56,57.03 75.57,57.03 75.57,58.62 75.98,59.03 76.31,59.03 76.5,59.22 v1(76.5,59.33)
  ART04 w0.173: v1(13.72,72.98) 13.47,73.24 13.47,73.86 14.13,74.52 15.11,74.52 15.34,74.3 15.8,74.3 16.03,74.52 16.49,74.52 18.11,76.14 27.7,76.14 27.87,75.97 27.87,75.81 28.04,75.64 28.39,75.64 28.56,75.81 28.56,75.97 28.74,76.14 29.08,76.14 29.25,75.97 29.25,75.81 29.48,75.59 29.72,75.59 29.94,75.81 29.94,75.97 30.12,76.14 30.89,76.14 32.28,74.75 56.01,74.75 61.26,69.49 68.69,69.49 69.18,69.01 69.72,68.65 69.88,68.58 76.45,68.58 77.17,67.86 77.17,59.2 77.02,59.06 77.02,59.06 76.77,59.06 v1(76.5,59.33)
SERDES_CLK0_N: length 105
  TOP w0.155: C171.2 50.48,112.67 49.89,112.67 v1(49.63,112.41)
  TOP w0.188: v1(89.96,46.57) 89.72,46.81 89.72,47.66 89.75,47.7 J16.32
  ART04 w0.173: v1(49.63,112.41) 49.84,112.62 51.31,112.62 53.83,110.1 53.83,80.64 61.99,72.48 68.46,72.48 69.5,73.52 74.74,73.52 78.17,72.1 81.55,68.72 81.55,54.1 81.76,53.88 81.76,46.56 84.26,44.06 89,44.06 89.7,44.75 89.7,46.3 v1(89.96,46.57)
SERDES_CLK0_P: length 105.7
  TOP w0.155: v1(49.63,113.33) 49.91,113.05 50.53,113.05 C170.2
  TOP w0.188: v1(89.04,46.57) 89.3,46.84 89.3,47.67 89.25,47.72 J16.34
  ART04 w0.173: v1(49.63,113.33) 49.92,113.04 51.48,113.04 54.24,110.27 54.24,109.61 54.56,109.29 54.56,108.91 54.24,108.6 54.24,108.22 54.56,107.91 54.56,107.53 54.24,107.22 54.24,106.84 54.56,106.52 54.56,106.15 54.24,105.83 54.24,105.46 54.56,105.14 54.56,104.77 54.24,104.45 54.24,104.08 54.56,103.76 54.56,103.39 54.24,103.07 54.24,80.82 62.16,72.89 68.29,72.89 69.33,73.93 74.83,73.93 78.41,72.45 81.96,68.9 81.96,54.27 82.18,54.05 82.18,46.73 84.44,44.47 88.83,44.47 89.28,44.92 89.28,46.33 v1(89.04,46.57)
SPI0_CLK: length 90.6
  TOP w0.203: v1(52.07,66.67) 52.65,67.26 R405.2 R88.2 51.33,64.52 51.33,60.86 50.29,59.82 50.29,58.67 50.5,58.47 J16.189 ; R641.1 v1(116.42,79.9)
  ART04 w0.203: v1(116.42,79.9) 113.27,83.06 110.54,83.06 108.72,84.88 102.46,84.88 101.86,84.28 92.96,84.28 92.48,83.79 90.9,83.79 90.59,83.49 84.9,83.49 84.7,83.28 83.85,83.28 82.3,84.84 76.24,84.84 74.06,82.67 73.67,82.67 72.7,81.7 65.49,81.7 62.87,79.07 v1(62.87,76.83)
  BOTTOM w0.203: v1(52.07,66.67) 52.7,66.67 v1(62.87,76.83)
SPI0_CLK_R: length 13.7
  TOP w0.203: R437.1 123.14,83.05 v1(123.07,83.05) ; v1(114.68,90.63) 115,90.3 U34.10
  ART04 w0.203: v1(123.07,83.05) 122.25,83.05 v1(114.68,90.63)
SPI0_CS0: length 86.4
  TOP w0.203: J16.193 49.5,58.31 49.81,58.62 49.81,60.6 v1(50.8,61.59) ; R634.1 v1(113.1,79.9)
  ART04 w0.203: v1(113.1,79.9) 112.31,80.68 108.14,80.68 107.52,81.31 105.67,81.31 104.96,80.59 102.44,80.59 101.09,81.95 90.99,81.95 89.59,80.55 84.97,80.55 84.75,80.33 83.73,80.33 81.87,82.19 81.31,82.19 81.2,82.3 79.13,82.3 78.89,82.06 77.78,82.06 77.54,82.3 76.2,82.3 75.65,81.75 75.65,81.25 75.03,80.63 75.03,80.06 73.99,79.02 68.86,79.02 v1(66.67,76.83)
  BOTTOM w0.203: v1(50.8,61.59) 50.8,60.95 51.88,59.87 53.05,59.87 56.49,63.31 56.49,63.75 56.7,63.96 57.14,63.96 57.35,64.17 57.35,64.62 57.56,64.82 58.01,64.82 58.21,65.03 58.21,65.48 58.42,65.69 58.87,65.69 59.08,65.9 59.08,66.34 59.29,66.55 59.73,66.55 67.39,74.21 67.39,76.12 v1(66.67,76.83)
SPI0_CS0_R: length 17.9
  TOP w0.203: v1(123.07,87.17) 123.14,87.17 R436.1 ; U34.13 113.05,88.18 v1(113.38,87.85)
  ART03 w0.203: v1(123.07,87.17) 122.24,86.33 117.67,86.33 117.49,86.51 117.49,87.58 117.32,87.76 117.06,87.76 116.88,87.58 116.88,86.51 116.71,86.33 116.45,86.33 116.28,86.51 116.28,87.58 116.1,87.76 115.84,87.76 115.67,87.58 115.67,86.51 115.49,86.33 114.55,86.33 113.38,87.51 v1(113.38,87.85)
SPI0_MISO: length 85.4
  TOP w0.203: J16.185 51.5,59.76 v1(52.07,60.33) ; R670.1 v1(115.31,79.9)
  ART04 w0.203: v1(62.87,75.56) 63.65,76.35 63.65,79.28 65.66,81.29 67.12,81.29 67.21,81.2 73.74,81.2 74.33,81.79 74.33,82.36 75.86,83.89 81.93,83.89 82.94,82.87 85.01,82.87 85.14,83.01 90.69,83.01 91.06,83.38 93.3,83.38 93.9,82.78 102.93,82.78 103.95,81.76 104.45,81.76 104.86,82.17 113.05,82.17 v1(115.31,79.9)
  BOTTOM w0.203: v1(62.87,75.56) 62.22,75.56 52.07,65.42 v1(52.07,60.33)
SPI0_MISO_R: length 13
  TOP w0.203: U34.11 114.35,88.18 v1(114.68,87.85) ; R438.1 123.14,81.99 v1(123.07,81.99)
  ART04 w0.203: v1(114.68,87.85) 116.52,87.85 122.37,81.99 v1(123.07,81.99)
SPI0_MOSI: length 86.8
  TOP w0.203: J16.187 51,59.94 51.92,60.86 51.92,62.2 52.96,63.25 R400.2 R87.2 53.09,64.39 v1(52.7,64.77) ; R620.1 v1(114.21,79.9)
  ART04 w0.203: v1(65.41,76.83) 65.41,78.3 66.68,79.58 72.57,79.58 72.99,80 73.84,80 75.25,81.42 75.25,81.92 76.03,82.7 77.71,82.7 77.95,82.46 78.73,82.46 78.96,82.7 81.37,82.7 81.48,82.6 81.88,82.6 82.11,82.83 82.41,82.83 82.77,82.47 83.22,82.47 84.72,80.98 89.23,80.98 91.23,82.98 92.87,82.98 93.47,82.37 102.73,82.37 103.75,81.36 104.98,81.36 105.39,81.76 112.35,81.76 v1(114.21,79.9)
  BOTTOM w0.203: v1(52.7,64.77) 54.56,64.77 55.69,65.9 55.69,66.41 55.94,66.66 56.3,66.66 56.55,66.92 56.55,67.27 56.81,67.53 57.16,67.53 57.42,67.78 57.42,68.14 57.67,68.39 58.03,68.39 58.28,68.64 58.28,69 58.53,69.25 58.89,69.25 59.14,69.5 59.14,69.86 59.4,70.11 59.75,70.11 60,70.37 60,70.72 60.26,70.98 60.61,70.98 60.87,71.23 60.87,71.59 61.12,71.84 61.48,71.84 61.73,72.09 61.73,72.45 61.98,72.7 62.34,72.7 62.59,72.96 62.59,73.31 62.85,73.56 63.2,73.56 63.45,73.82 63.45,74.17 63.71,74.43 64.06,74.43 64.32,74.68 64.32,75.04 64.57,75.29 64.93,75.29 65.18,75.54 65.18,75.9 65.41,76.12 v1(65.41,76.83)
SPI0_MOSI_R: length 14.6
  TOP w0.203: v1(114.66,87.02) 114.07,87.6 114.07,87.8 113.7,88.17 U34.12 ; v1(123.07,79.94) 123.14,79.94 R439.1
  ART04 w0.203: v1(123.07,79.94) 115.99,87.02 v1(114.66,87.02)
SPI2_CLK: length 30.4
  TOP w0.203: v1(65.91,47.88) 65.91,46.25 67.66,44.51 68.24,44.51 69.16,43.59 69.16,41.73 68.68,41.25 R413.2 R414.1 ; J16.177 53.5,58.95 v1(53.42,59.03)
  ART04 w0.203: v1(65.91,47.88) 65.91,49.25 64.01,51.16 61.01,51.16 53.82,58.34 53.82,58.62 v1(53.42,59.03)
SPI2_CS0: length 37.2
  TOP w0.203: J16.181 52.5,57.41 52.15,57.76 v1(52.15,59.03) ; R415.1 75.18,42.21 R412.1 74.8,42.11 74.37,42.54 74.37,43.48 73.48,44.37 70.48,44.37 70.08,43.97 70.08,43.01 v1(69.62,42.55)
  ART04 w0.203: v1(52.15,59.03) 63.78,47.4 65.18,47.4 66.24,46.33 66.24,45.46 68.34,43.37 69.24,43.37 69.62,42.98 v1(69.62,42.55)
SPI2_MISO: length 70.1
  TOP w0.203: R420.1 89.66,41.12 R423.1 89.07,43.52 88.68,43.91 87.55,44.38 83.29,44.38 v1(83.03,44.64) ; J16.173 54.5,58.84 v1(54.69,59.03)
  ART04 w0.203: v1(70.96,73.07) 71.32,72.71 72.15,72.36 73.49,72.36 78.03,71.46 80.19,69.3 80.74,67.97 80.74,59.87 80.5,59.63 80.5,53.89 80.74,53.65 80.74,47.32 81.02,46.65 v1(83.03,44.64)
  BOTTOM w0.203: v1(70.96,73.07) 70.42,72.54 69.75,72.54 67.31,71.53 63.34,68.88 56.36,61.9 55.97,60.95 v1(54.69,59.03)
SPI2_MOSI: length 64.2
  TOP w0.203: J16.175 54,59.61 v1(54.69,60.3) ; R421.2 82.32,41.98 R422.1 82.42,42.6 v1(82.52,42.71)
  ART04 w0.203: v1(70.1,73.07) 70.42,72.75 70.43,72.75 71.04,72.14 71.9,71.79 73.61,71.79 77.36,71.04 79.48,68.92 80.07,67.47 80.07,53.53 80.24,53.37 80.24,47.34 81.9,43.33 v1(82.52,42.71)
  BOTTOM w0.203: v1(54.69,60.3) 55.04,61.15 63.47,69.58 67.12,72.02 69.66,73.07 v1(70.1,73.07)
SPI_CLK_HUB0: length 32.5
  TOP w0.203: v1(102.52,89.66) 102.55,89.64 R587.1 ; U38.34 86.29,103.62 86.39,103.87 86.39,104.18 v1(86.72,104.51)
  ART03 w0.203: v1(86.72,104.51) 88.88,104.51 92.75,100.63 94.41,100.63 95.63,101.85 97.78,101.85 99.71,99.92 100.69,99.92 104.55,96.07 104.55,92.4 102.52,90.38 v1(102.52,89.66)
SPI_CS_HUB: length 100.3
  TOP w0.188: R588.2 101.36,88.09 101.82,87.62 v1(101.88,87.62)
  TOP w0.203: R563.2 R630.1 R631.1 v1(29.59,115.19)
  ART03 w0.203: v1(29.59,115.19) 34.44,110.34 34.44,107.1 38.55,103 39.03,103 39.17,102.85 45.41,102.85 45.43,102.83 45.61,102.83 49.32,99.11 66.97,99.11 67.14,99.29 67.14,99.44 67.32,99.62 67.58,99.62 67.75,99.44 67.75,99.29 67.93,99.11 68.19,99.11 68.36,99.29 68.36,99.44 68.54,99.62 68.79,99.62 68.97,99.44 68.97,99.29 69.15,99.11 70.47,99.11 72.52,101.17 82.4,101.17 83.39,100.18 83.39,99.75 84.48,98.65 85.01,98.65 85.17,98.81 85.57,98.81 85.88,98.5 85.88,96.44 86.32,96 92.29,96 93.29,97 97.38,97 99.62,94.76 99.62,90.88 98.92,90.19 98.92,87.58 99.34,87.16 101.43,87.16 v1(101.88,87.62)
SPI_CS_HUB0: length 31.3
  TOP w0.203: R588.1 v1(101.21,89.66) ; U38.32 87.09,102.08 86.83,101.81 86.54,101.81 v1(86.49,101.87)
  ART03 w0.203: v1(86.49,101.87) 86.91,102.29 90.52,102.29 93.1,99.71 94.06,99.71 95.8,101.45 96.8,101.45 98.73,99.52 100.52,99.52 101.19,98.84 101.19,97.6 104.14,94.65 104.14,92.57 103.87,92.3 103.85,92.3 v1(101.21,89.66)
SPI_CS_HUB1: length 7.2
  TOP w0.203: U36.45 96.55,84.11 v1(96.84,83.82) ; R584.1 v1(101.21,86.49)
  ART03 w0.203: v1(101.21,86.49) 98.54,83.82 v1(96.84,83.82)
SPI_MISO_HUB: length 100.3
  TOP w0.188: v1(99.53,88.51) 99.95,88.09 R581.2
  TOP w0.203: R562.1 29.21,117.22 v1(29.46,116.97)
  ART03 w0.203: v1(99.53,88.51) 99.33,88.71 99.33,90.02 100.03,90.71 100.03,94.93 97.55,97.41 91.34,97.41 90.33,96.4 86.78,96.4 86.33,96.85 86.33,99.07 84.95,100.46 83.91,100.46 82.79,101.57 72.36,101.57 71.16,100.38 58.44,100.38 58.26,100.2 58.26,99.8 58.08,99.62 57.83,99.62 57.65,99.8 57.65,100.2 57.47,100.38 57.22,100.38 57.04,100.2 57.04,99.8 56.86,99.62 56.61,99.62 56.43,99.8 56.43,100.2 56.25,100.38 56,100.38 55.82,100.2 55.82,99.8 55.64,99.62 55.39,99.62 55.21,99.8 55.21,100.2 55.03,100.38 54.78,100.38 54.6,100.2 54.6,99.8 54.42,99.62 54.17,99.62 53.99,99.8 53.99,100.2 53.81,100.38 53.56,100.38 53.38,100.2 53.38,99.8 53.2,99.62 52.95,99.62 52.77,99.8 52.77,100.2 52.59,100.38 52.34,100.38 52.16,100.2 52.16,99.8 51.98,99.62 51.73,99.62 51.55,99.8 51.55,100.2 51.37,100.38 48.63,100.38 45.75,103.26 39.34,103.26 39.2,103.4 38.72,103.4 34.85,107.27 34.85,111.13 29.46,116.51 v1(29.46,116.97)
SPI_MISO_HUB0: length 32.3
  TOP w0.203: U38.33 86.69,103.51 v1(86.97,103.78) ; R585.1 v1(100.19,89.66)
  ART03 w0.203: v1(86.97,103.78) 86.03,102.84 86.03,101.68 86.34,101.37 90.86,101.37 92.93,99.31 95.06,99.31 96.18,100.43 97.24,100.43 99.29,98.37 100.39,98.37 100.79,97.98 100.79,97.28 103.07,95 103.07,92.52 102.81,92.25 102.79,92.25 v1(100.19,89.66)
SPI_MISO_HUB1: length 6.8
  TOP w0.203: U36.46 96.15,83.89 v1(96.08,83.82) ; R581.1 v1(100.19,86.49)
  ART03 w0.203: v1(96.08,83.82) 96.56,84.3 97.26,84.3 99.44,86.49 v1(100.19,86.49)
SPI_MOSI_HUB: length 112.4
  TOP w0.188: v1(99.53,87.62) 99.47,87.62 99,88.09 R582.2
  TOP w0.203: R567.1 v1(15.75,118.36)
  ART03 w0.203: v1(99.53,87.62) 99.99,88.08 99.99,88.7 99.74,88.95 99.74,89.85 102.06,92.17 102.06,94.05 97.17,98.94 97.17,99.35 96.9,99.62 96.52,99.62 95.4,98.49 92.59,98.49 90.53,100.56 86,100.56 85.07,101.49 85.07,101.7 84.39,102.39 79.49,102.39 78.93,102.95 78.55,102.95 77.99,102.39 72.02,102.39 70.82,101.19 48.97,101.19 46.09,104.07 39.68,104.07 39.54,104.22 39.05,104.22 35.66,107.61 35.66,114.21 32.19,117.68 31.54,117.68 30.53,118.69 16.07,118.69 v1(15.75,118.36)
SPI_MOSI_HUB0: length 34.9
  TOP w0.203: v1(85.67,104.5) 85.67,104.14 85.89,103.92 U38.35 ; v1(102.62,92.71) 102.62,91.57 101.17,90.12 99.67,90.12 98.86,89.31 R586.1
  ART03 w0.203: v1(102.62,92.71) 102.62,94.88 100.52,96.98 100.12,96.98 97.07,100.03 96.35,100.03 95.23,98.9 92.76,98.9 90.7,100.97 86.17,100.97 85.62,101.51 85.62,101.98 84.84,102.77 84.84,103.82 85.51,104.5 v1(85.67,104.5)
SPI_MOSI_HUB1: length 4.9
  TOP w0.203: R582.1 98.86,86.51 97.92,85.57 96.27,85.57 95.75,85.06 U36.47
SPI_SCK_HUB: length 110.3
  TOP w0.203: R587.2 102.85,88.09 103.11,88.34 103.11,92.98 102.74,93.34 102.01,93.34 101.6,92.94 v1(101.6,92.71) ; R561.2 v1(15.75,117.35)
  ART03 w0.203: v1(15.75,117.35) 16.48,118.08 29.91,118.08 31.25,116.74 31.79,116.74 32.36,116.17 32.78,116.17 35.25,113.7 35.25,107.44 38.88,103.81 39.37,103.81 39.51,103.67 45.92,103.67 48.8,100.79 70.99,100.79 72.19,101.98 82.96,101.98 84.08,100.86 85.12,100.86 85.83,100.15 90.36,100.15 92.42,98.09 96.32,98.09 96.66,98.42 97.11,98.42 101.6,93.93 v1(101.6,92.71)
SPI_SCK_HUB1: length 7.4
  TOP w0.203: U36.44 96.95,85.06 97.1,85.22 98.15,85.22 98.78,85.85 101.88,85.85 102.31,86.28 102.31,87.04 R583.1
SPWR_DET_REAR_HUB1: length 8.6
  TOP w0.203: U38.44 84.45,99.77 v1(84.68,100) ; R576.1 v1(81.66,105.79)
  ART04 w0.203: v1(81.66,105.79) 82.43,105.02 82.43,102.92 84.68,100.66 v1(84.68,100)
SPWR_DET_USB2: length 3.4
  TOP w0.203: U36.76 90.94,76.05 89.9,75.01 89.56,75.01 88.93,74.37 R467.2
SYS_RST_IN: length 52.7
  TOP w0.203: v1(104.85,53.19) 104.27,53.77 104.27,54.46 104,54.73 J16.297 ; v1(126.36,25.7) 126.87,25.2 126.87,22.63 127.15,22.35 128.42,22.35 R463.1
  ART04 w0.203: v1(104.85,53.19) 104.85,49.64 106,48.49 106,37.93 110.02,33.91 111.1,33.91 111.51,33.5 112.93,33.5 117.91,28.52 124.05,28.52 124.89,27.69 126.36,27.69 126.87,27.18 126.87,26.21 v1(126.36,25.7)
SYS_RST_IN_R: length 10.7
  TOP w0.203: S3.1 S3.2 131.49,20.19 C286.2 R463.2 130.33,20.82 130.12,20.62 128.13,20.62 127.88,20.86 R464.1
TAISHAN_POWEROFF_IN: length 46
  TOP w0.203: J16.299 103.5,54.53 v1(103.58,54.46) ; R465.1 v1(126.38,26.85)
  ART04 w0.203: v1(126.38,26.85) 125.08,26.85 123.86,28.07 116.49,28.07 112.17,32.38 109.94,32.38 105.54,36.79 105.54,47.93 104.22,49.25 104.22,53.82 v1(103.58,54.46)
TAISHAN_POWEROFF_IN_R: length 10.7
  TOP w0.203: R465.2 127.88,26.45 128.13,26.2 130.12,26.2 130.33,26.41 R466.1 C287.2 131.49,25.78 S2.2 S2.1
TAISHAN_SLEEP_IN: length 35.1
  TOP w0.203: v1(121.26,50.67) 131.01,50.67 132.85,52.51 SW1.1 ; J16.291 105.5,55.13 105.94,54.69 108.25,54.69 108.83,55.27 114.73,55.27 115.44,54.56 v1(115.44,51.05)
  ART03 w0.203: v1(115.44,51.05) 115.82,50.67 v1(121.26,50.67)
TAISHAN_SLEEP_OUT: length 34.2
  TOP w0.203: R291.1 v1(108.58,81.3) ; v1(109.61,57.13) 108.89,56.41 108.89,56.13 107.93,55.18 106.19,55.18 106,55.37 J16.289
  ART03 w0.203: v1(108.58,81.3) 109.65,80.24 109.65,78.55 110.95,77.26 110.95,71.52 110.49,71.06 110.49,66.65 112.53,64.61 112.53,59.11 111.2,57.78 110.25,57.78 v1(109.61,57.13)
TAISHAN_SLEEP_OUT_R: length 136.3
  TOP w0.203: R290.1 92.87,12.79 v1(93.1,12.56) ; v1(78.49,79.11) 77.84,78.46 U24.11
  ART03 w0.203: v1(96.39,47.24) 97.96,48.81 101.91,48.81 102.45,49.35 104.11,49.35 104.72,49.96 111.29,49.96 113.12,51.79 115.48,51.79 116.65,52.96 122.38,52.96 v1(123.01,53.59) ; v1(93.1,12.56) 95.2,14.66 95.2,19.4 93.47,21.13 93.47,31.32 94.79,32.64 v1(95.25,32.64)
  ART04 w0.203: v1(96.39,47.24) 96.39,46.79 96.42,46.76 96.42,45.86 97.92,44.35 97.92,35.12 95.44,32.64 v1(95.25,32.64) ; v1(123.01,53.59) 123.01,58.24 117.98,63.27 117.98,68.4 115.24,71.15 109.32,71.15 108.83,71.63 106.42,71.63 105.64,72.42 101.17,72.42 100.51,73.08 100.51,75.2 99.64,76.07 95.55,76.07 92.84,78.79 91.95,78.79 91.87,78.87 91.51,78.87 89.67,77.03 89.67,76.81 88.88,76.02 86.67,76.02 85.76,75.11 85.04,75.11 82.82,77.33 81.17,77.33 80.72,77.77 80.34,77.77 79,79.11 v1(78.49,79.11)
TYPE_ID0: length 5.1
  TOP w0.203: U19.19 112.26,95.34 112.05,95.12 R530.2 111.35,94.84 111.12,94.61 109.55,94.61 109.27,94.89 R514.1
TYPE_ID1: length 5.3
  TOP w0.203: U19.20 112.29,94.69 111.71,94.11 R531.2 111.35,93.83 111.12,93.6 109.55,93.6 109.27,93.88 R515.1
TYPEC_CC1: length 39.6
  TOP w0.203: U6.3 v1(104.52,12.01) ; v1(98.1,25.09) U7.2 98.1,22.53 98.06,22.5 C120.2 R246.2 ; v1(104.9,7.65) 105.1,7.45 J4.5
  ART03 w0.203: v1(104.52,12.01) 104.52,9.2 104.9,8.82 v1(104.9,7.65)
  ART04 w0.203: v1(98.1,25.09) 100.69,22.5 108.6,22.5 110.04,21.91 112.11,19.84 112.11,16.87 110.22,14.98 106.78,14.98 104.52,12.72 v1(104.52,12.01)
